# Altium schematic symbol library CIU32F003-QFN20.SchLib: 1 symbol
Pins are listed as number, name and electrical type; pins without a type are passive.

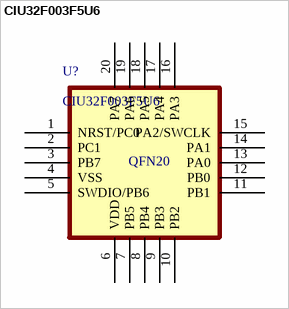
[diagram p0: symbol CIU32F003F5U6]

## CIU32F003F5U6
designator U?
footprint CIU32F003-QFN20 (QFN, 20-Leads, Body 3.0x3.0mm (max), Pitch 0.40mm, IPC Medium Density)
pins: 1 NRST/PC0, 2 PC1, 3 PB7, 4 VSS, 5 SWDIO/PB6, 6 VDD, 7 PB5, 8 PB4, 9 PB3, 10 PB2, 11 PB1, 12 PB0, 13 PA0, 14 PA1, 15 PA2/SWCLK, 16 PA3, 17 PA4, 18 PA5, 19 PA6, 20 PA7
